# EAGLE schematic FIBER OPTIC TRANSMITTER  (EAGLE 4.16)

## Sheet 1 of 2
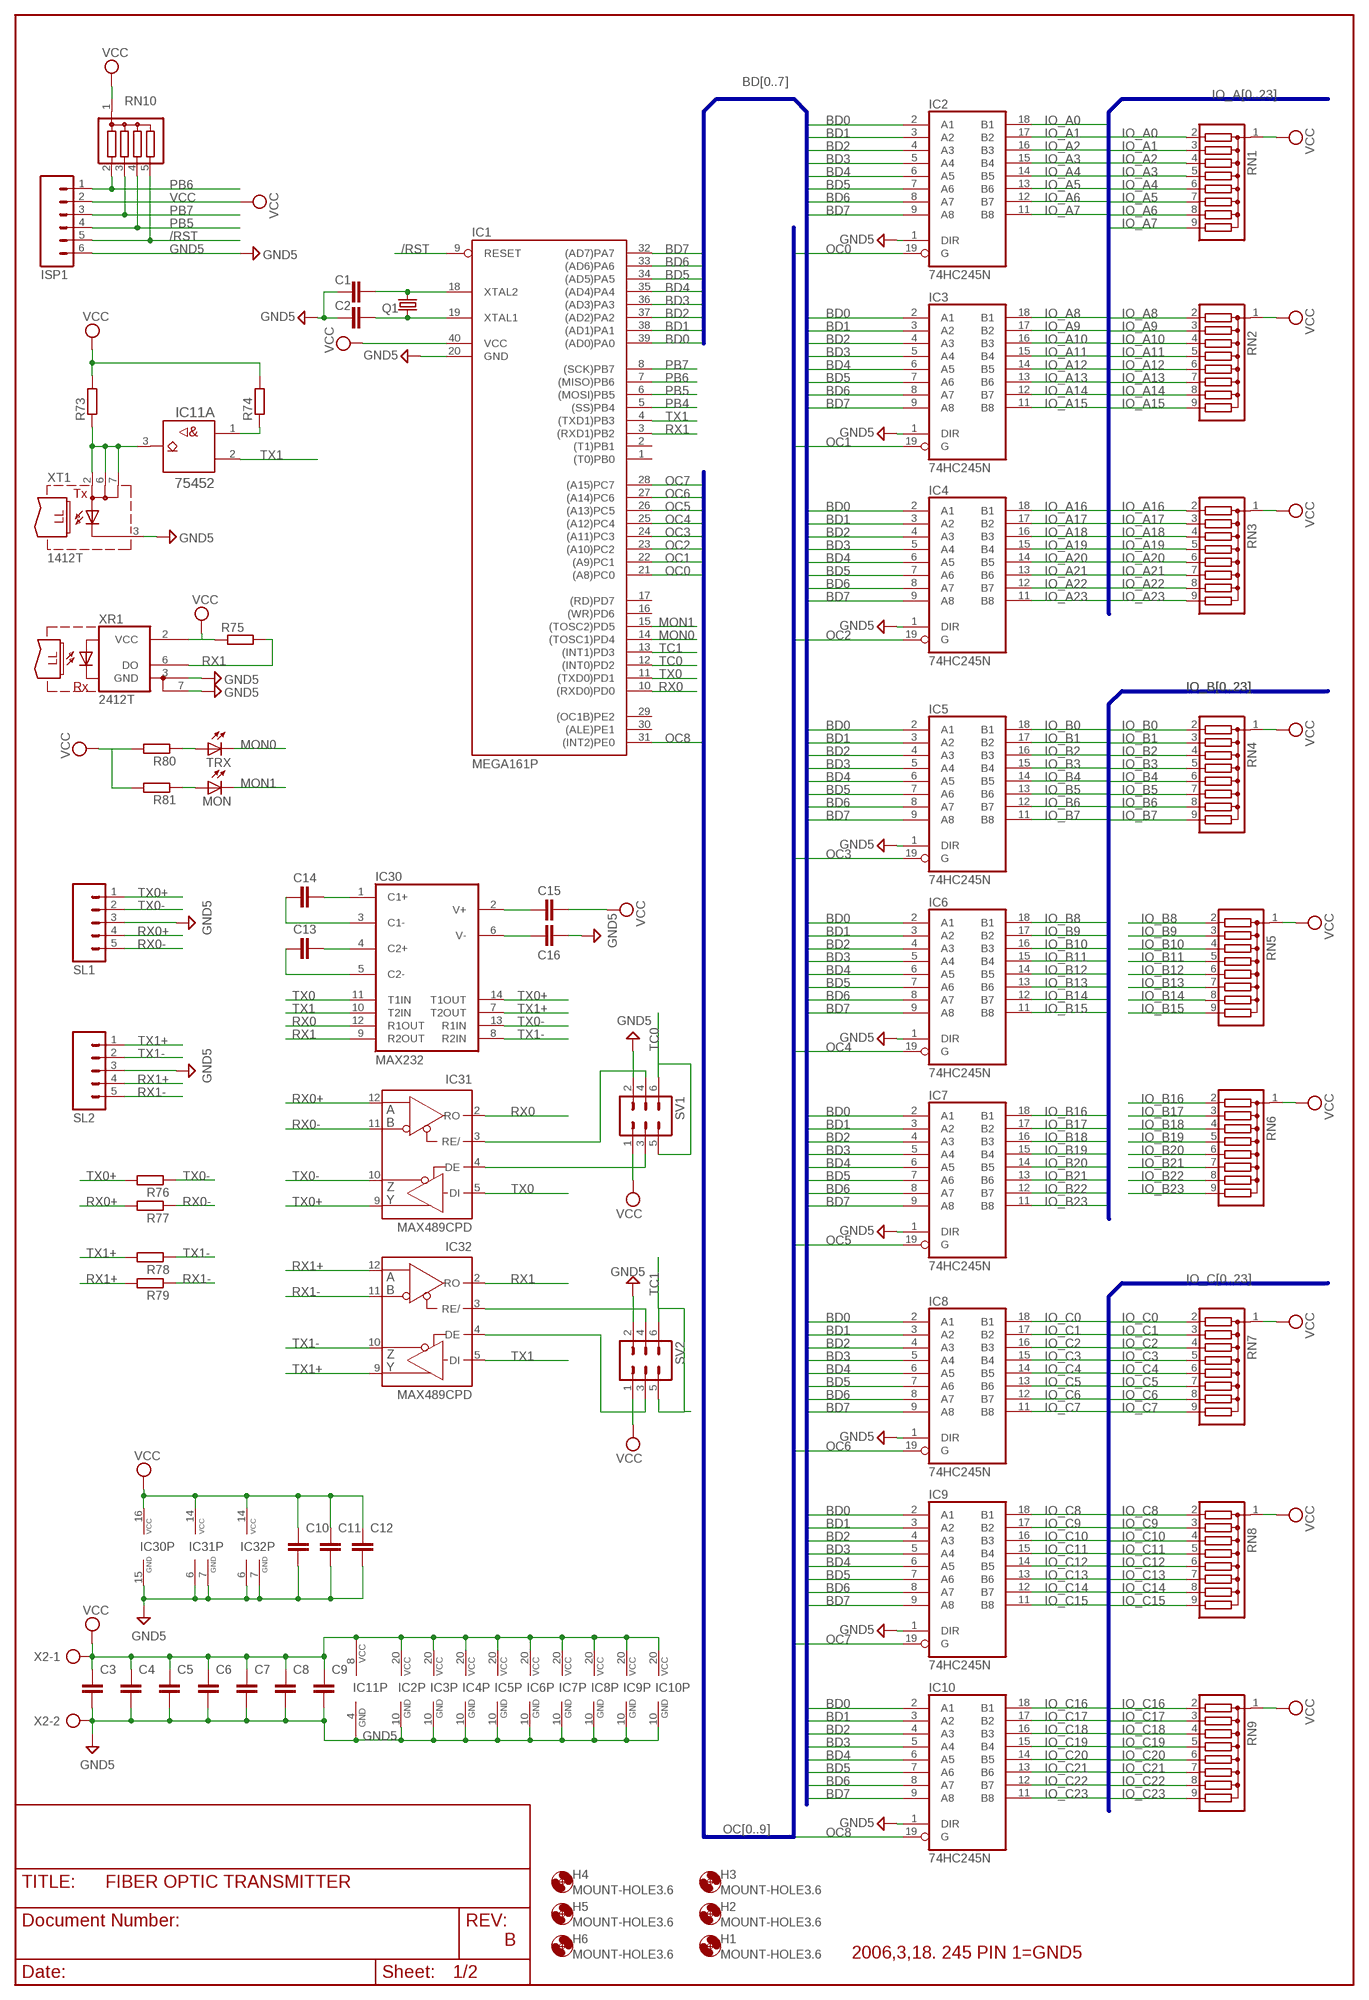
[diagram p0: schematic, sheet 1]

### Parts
C1  C5/2.5  [C5B2.5]
C2  C5/2.5  [C5B2.5]
C3  C5/2.5  [C5B2.5]
C4  C5/2.5  [C5B2.5]
C5  C5/2.5  [C5B2.5]
C6  C5/2.5  [C5B2.5]
C7  C5/2.5  [C5B2.5]
C8  C5/2.5  [C5B2.5]
C9  C5/2.5  [C5B2.5]
C10  C5/2.5  [C5B2.5]
C11  C5/2.5  [C5B2.5]
C12  C5/2.5  [C5B2.5]
C13  C5/2.5  [C5B2.5]
C14  C5/2.5  [C5B2.5]
C15  C5/2.5  [C5B2.5]
C16  C5/2.5  [C5B2.5]
H1  MOUNT-HOLE3.6  [3,6]
H2  MOUNT-HOLE3.6  [3,6]
H3  MOUNT-HOLE3.6  [3,6]
H4  MOUNT-HOLE3.6  [3,6]
H5  MOUNT-HOLE3.6  [3,6]
H6  MOUNT-HOLE3.6  [3,6]
IC1  MEGA161P  [DIL40]
IC2  74HC245N  [DIL20]
IC3  74HC245N  [DIL20]
IC4  74HC245N  [DIL20]
IC5  74HC245N  [DIL20]
IC6  74HC245N  [DIL20]
IC7  74HC245N  [DIL20]
IC8  74HC245N  [DIL20]
IC9  74HC245N  [DIL20]
IC10  74HC245N  [DIL20]
IC11  75452  75451  [DIL08]
IC30  MAX232  [DIL16]
IC31  MAX489CPD  [DIL14]
IC32  MAX489CPD  [DIL14]
ISP1  MA06  [06PA]
MON  LEDB156  [Q62902-B156]
Q1  CRYTALHC18U-V  [HC18U-V]
R73  R-EU_0207/10  [0207/10]
R74  R-EU_0207/10  [0207/10]
R75  R-EU_0207/10  [0207/10]
R76  R-EU_0207/10  [0207/10]
R77  R-EU_0207/10  [0207/10]
R78  R-EU_0207/10  [0207/10]
R79  R-EU_0207/10  [0207/10]
R80  R-EU_0207/10  [0207/10]
R81  R-EU_0207/10  [0207/10]
RN1  G08R  [SIL9]
RN2  G08R  [SIL9]
RN3  G08R  [SIL9]
RN4  G08R  [SIL9]
RN5  G08R  [SIL9]
RN6  G08R  [SIL9]
RN7  G08R  [SIL9]
RN8  G08R  [SIL9]
RN9  G08R  [SIL9]
RN10  G04R  [SIL5]
SL1  M05  [05P]
SL2  M05  [05P]
SV1  MA03-2  [MA03-2]
SV2  MA03-2  [MA03-2]
TRX  LEDB156  [Q62902-B156]
X2  AK500/2  [AK500/2]
XR1  2412T  HFBR-2412T  [HFBR-X41XT]
XT1  1412T  HFBR-1412T  [HFBR-X41XT]

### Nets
/RST: IC1.9(RESET) ISP1.5 RN10.5
BD0: IC1.39((AD0)PA0) IC2.2(A1) IC3.2(A1) IC4.2(A1) IC5.2(A1) IC6.2(A1) IC7.2(A1) IC8.2(A1) IC9.2(A1) IC10.2(A1)
BD1: IC1.38((AD1)PA1) IC2.3(A2) IC3.3(A2) IC4.3(A2) IC5.3(A2) IC6.3(A2) IC7.3(A2) IC8.3(A2) IC9.3(A2) IC10.3(A2)
BD2: IC1.37((AD2)PA2) IC2.4(A3) IC3.4(A3) IC4.4(A3) IC5.4(A3) IC6.4(A3) IC7.4(A3) IC8.4(A3) IC9.4(A3) IC10.4(A3)
BD3: IC1.36((AD3)PA3) IC2.5(A4) IC3.5(A4) IC4.5(A4) IC5.5(A4) IC6.5(A4) IC7.5(A4) IC8.5(A4) IC9.5(A4) IC10.5(A4)
BD4: IC1.35((AD4)PA4) IC2.6(A5) IC3.6(A5) IC4.6(A5) IC5.6(A5) IC6.6(A5) IC7.6(A5) IC8.6(A5) IC9.6(A5) IC10.6(A5)
BD5: IC1.34((AD5)PA5) IC2.7(A6) IC3.7(A6) IC4.7(A6) IC5.7(A6) IC6.7(A6) IC7.7(A6) IC8.7(A6) IC9.7(A6) IC10.7(A6)
BD6: IC1.33((AD6)PA6) IC2.8(A7) IC3.8(A7) IC4.8(A7) IC5.8(A7) IC6.8(A7) IC7.8(A7) IC8.8(A7) IC9.8(A7) IC10.8(A7)
BD7: IC1.32((AD7)PA7) IC2.9(A8) IC3.9(A8) IC4.9(A8) IC5.9(A8) IC6.9(A8) IC7.9(A8) IC8.9(A8) IC9.9(A8) IC10.9(A8)
GND5: C1.1 C2.1 C3.2 C4.2 C5.2 C6.2 C7.2 C8.2 C9.2 C10.2 C11.2 C12.2 C16.1 IC1.20(GND) IC2.1(DIR) IC2.10(GND) IC3.1(DIR) IC3.10(GND) IC4.1(DIR) IC4.10(GND) IC5.1(DIR) IC5.10(GND) IC6.1(DIR) IC6.10(GND) IC7.1(DIR) IC7.10(GND) IC8.1(DIR) IC8.10(GND) IC9.1(DIR) IC9.10(GND) IC10.1(DIR) IC10.10(GND) IC11.4(P:GND) IC30.15(GND) IC31.6(GND) IC31.7(GND) IC32.6(GND) IC32.7(GND) ISP1.6 SL1.3 SL2.3 SV1.2 SV2.2 X2.2 XR1.3(GND) XR1.7(GND1) XT1.3(C) ; also sheet 2
IO_A0: IC2.18(B1) RN1.2 ; also sheet 2
IO_A1: IC2.17(B2) RN1.3 ; also sheet 2
IO_A2: IC2.16(B3) RN1.4 ; also sheet 2
IO_A3: IC2.15(B4) RN1.5 ; also sheet 2
IO_A4: IC2.14(B5) RN1.6 ; also sheet 2
IO_A5: IC2.13(B6) RN1.7 ; also sheet 2
IO_A6: IC2.12(B7) RN1.8 ; also sheet 2
IO_A7: IC2.11(B8) RN1.9 ; also sheet 2
IO_A8: IC3.18(B1) RN2.2 ; also sheet 2
IO_A9: IC3.17(B2) RN2.3 ; also sheet 2
IO_A10: IC3.16(B3) RN2.4 ; also sheet 2
IO_A11: IC3.15(B4) RN2.5 ; also sheet 2
IO_A12: IC3.14(B5) RN2.6 ; also sheet 2
IO_A13: IC3.13(B6) RN2.7 ; also sheet 2
IO_A14: IC3.12(B7) RN2.8 ; also sheet 2
IO_A15: IC3.11(B8) RN2.9 ; also sheet 2
IO_A16: IC4.18(B1) RN3.2 ; also sheet 2
IO_A17: IC4.17(B2) RN3.3 ; also sheet 2
IO_A18: IC4.16(B3) RN3.4 ; also sheet 2
IO_A19: IC4.15(B4) RN3.5 ; also sheet 2
IO_A20: IC4.14(B5) RN3.6 ; also sheet 2
IO_A21: IC4.13(B6) RN3.7 ; also sheet 2
IO_A22: IC4.12(B7) RN3.8 ; also sheet 2
IO_A23: IC4.11(B8) RN3.9 ; also sheet 2
IO_B0: IC5.18(B1) RN4.2 ; also sheet 2
IO_B1: IC5.17(B2) RN4.3 ; also sheet 2
IO_B2: IC5.16(B3) RN4.4 ; also sheet 2
IO_B3: IC5.15(B4) RN4.5 ; also sheet 2
IO_B4: IC5.14(B5) RN4.6 ; also sheet 2
IO_B5: IC5.13(B6) RN4.7 ; also sheet 2
IO_B6: IC5.12(B7) RN4.8 ; also sheet 2
IO_B7: IC5.11(B8) RN4.9 ; also sheet 2
IO_B8: IC6.18(B1) RN5.2 ; also sheet 2
IO_B9: IC6.17(B2) RN5.3 ; also sheet 2
IO_B10: IC6.16(B3) RN5.4 ; also sheet 2
IO_B11: IC6.15(B4) RN5.5 ; also sheet 2
IO_B12: IC6.14(B5) RN5.6 ; also sheet 2
IO_B13: IC6.13(B6) RN5.7 ; also sheet 2
IO_B14: IC6.12(B7) RN5.8 ; also sheet 2
IO_B15: IC6.11(B8) RN5.9 ; also sheet 2
IO_B16: IC7.18(B1) RN6.2 ; also sheet 2
IO_B17: IC7.17(B2) RN6.3 ; also sheet 2
IO_B18: IC7.16(B3) RN6.4 ; also sheet 2
IO_B19: IC7.15(B4) RN6.5 ; also sheet 2
IO_B20: IC7.14(B5) RN6.6 ; also sheet 2
IO_B21: IC7.13(B6) RN6.7 ; also sheet 2
IO_B22: IC7.12(B7) RN6.8 ; also sheet 2
IO_B23: IC7.11(B8) RN6.9 ; also sheet 2
IO_C0: IC8.18(B1) RN7.2 ; also sheet 2
IO_C1: IC8.17(B2) RN7.3 ; also sheet 2
IO_C2: IC8.16(B3) RN7.4 ; also sheet 2
IO_C3: IC8.15(B4) RN7.5 ; also sheet 2
IO_C4: IC8.14(B5) RN7.6 ; also sheet 2
IO_C5: IC8.13(B6) RN7.7 ; also sheet 2
IO_C6: IC8.12(B7) RN7.8 ; also sheet 2
IO_C7: IC8.11(B8) RN7.9 ; also sheet 2
IO_C8: IC9.18(B1) RN8.2 ; also sheet 2
IO_C9: IC9.17(B2) RN8.3 ; also sheet 2
IO_C10: IC9.16(B3) RN8.4 ; also sheet 2
IO_C11: IC9.15(B4) RN8.5 ; also sheet 2
IO_C12: IC9.14(B5) RN8.6 ; also sheet 2
IO_C13: IC9.13(B6) RN8.7 ; also sheet 2
IO_C14: IC9.12(B7) RN8.8 ; also sheet 2
IO_C15: IC9.11(B8) RN8.9 ; also sheet 2
IO_C16: IC10.18(B1) RN9.2 ; also sheet 2
IO_C17: IC10.17(B2) RN9.3 ; also sheet 2
IO_C18: IC10.16(B3) RN9.4 ; also sheet 2
IO_C19: IC10.15(B4) RN9.5 ; also sheet 2
IO_C20: IC10.14(B5) RN9.6 ; also sheet 2
IO_C21: IC10.13(B6) RN9.7 ; also sheet 2
IO_C22: IC10.12(B7) RN9.8 ; also sheet 2
IO_C23: IC10.11(B8) RN9.9 ; also sheet 2
MON0: IC1.14((TOSC1)PD4) TRX.K(C)
MON1: IC1.15((TOSC2)PD5) MON.K(C)
N$73: IC11.3(A:Y) R73.1 XT1.2(A) XT1.6(A1) XT1.7(A2)
N$74: C1.2 IC1.18(XTAL2) Q1.2
N$75: IC11.1(A:A) R74.1
N$76: C2.2 IC1.19(XTAL1) Q1.1
N$77: C16.2 IC30.6(V-)
N$78: R80.1 TRX.A
N$79: MON.A R81.1
N$80: IC31.3(RE/) SV1.4
N$81: IC31.4(DE) SV1.3
N$82: IC32.3(RE/) SV2.4
N$83: IC32.4(DE) SV2.3
N$103: C14.1 IC30.1(C1+)
N$104: C14.2 IC30.3(C1-)
N$105: C13.1 IC30.4(C2+)
N$106: C13.2 IC30.5(C2-)
N$107: C15.1 IC30.2(V+)
OC0: IC1.21((A8)PC0) IC2.19(G)
OC1: IC1.22((A9)PC1) IC3.19(G)
OC2: IC1.23((A10)PC2) IC4.19(G)
OC3: IC1.24((A11)PC3) IC5.19(G)
OC4: IC1.25((A12)PC4) IC6.19(G)
OC5: IC1.26((A13)PC5) IC7.19(G)
OC6: IC1.27((A14)PC6) IC8.19(G)
OC7: IC1.28((A15)PC7) IC9.19(G)
OC8: IC1.31((INT2)PE0) IC10.19(G)
PB4: IC1.5((SS)PB4)
PB5: IC1.6((MOSI)PB5) ISP1.4 RN10.4
PB6: IC1.7((MISO)PB6) ISP1.1 RN10.2
PB7: IC1.8((SCK)PB7) ISP1.3 RN10.3
RX0: IC1.10((RXD0)PD0) IC30.12(R1OUT) IC31.2(RO)
RX0+: IC31.12(A) R77.2 SL1.4
RX0-: IC31.11(B) R77.1 SL1.5
RX1: IC1.3((RXD1)PB2) IC30.9(R2OUT) IC32.2(RO) R75.2 XR1.6(DO)
RX1+: IC32.12(A) R79.2 SL2.4
RX1-: IC32.11(B) R79.1 SL2.5
TC0: IC1.12((INT0)PD2) SV1.5 SV1.6
TC1: IC1.13((INT1)PD3) SV2.5 SV2.6
TX0: IC1.11((TXD0)PD1) IC30.11(T1IN) IC31.5(DI)
TX0+: IC30.14(T1OUT) IC31.9(Y) R76.2 SL1.1
TX0-: IC30.13(R1IN) IC31.10(Z) R76.1 SL1.2
TX1: IC1.4((TXD1)PB3) IC11.2(A:B) IC30.10(T2IN) IC32.5(DI)
TX1+: IC30.7(T2OUT) IC32.9(Y) R78.2 SL2.1
TX1-: IC30.8(R2IN) IC32.10(Z) R78.1 SL2.2
VCC: C3.1 C4.1 C5.1 C6.1 C7.1 C8.1 C9.1 C10.1 C11.1 C12.1 C15.2 IC1.40(VCC) IC2.20(VCC) IC3.20(VCC) IC4.20(VCC) IC5.20(VCC) IC6.20(VCC) IC7.20(VCC) IC8.20(VCC) IC9.20(VCC) IC10.20(VCC) IC11.8(P:VCC) IC30.16(VCC) IC31.14(VCC) IC32.14(VCC) ISP1.2 R73.2 R74.2 R75.1 R80.2 R81.2 RN1.1 RN2.1 RN3.1 RN4.1 RN5.1 RN6.1 RN7.1 RN8.1 RN9.1 RN10.1 SV1.1 SV2.1 X2.1 XR1.2(VCC)
Unconnected: IC1.1((T0)PB0) IC1.2((T1)PB1) IC1.16((WR)PD6) IC1.17((RD)PD7) IC1.29((OC1B)PE2) IC1.30((ALE)PE1) IC11.5(B:Y) IC11.6(B:A) IC11.7(B:B) IC31.1(NC) IC31.8(NC) IC31.13(NC) IC32.1(NC) IC32.8(NC) IC32.13(NC)

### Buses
BD[0..7]
OC[0..9]
IO_A[0..23]
IO_C[0..23]
IO_B[0..23]

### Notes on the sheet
- B
- 2006,3,18. 245 PIN 1=GND5

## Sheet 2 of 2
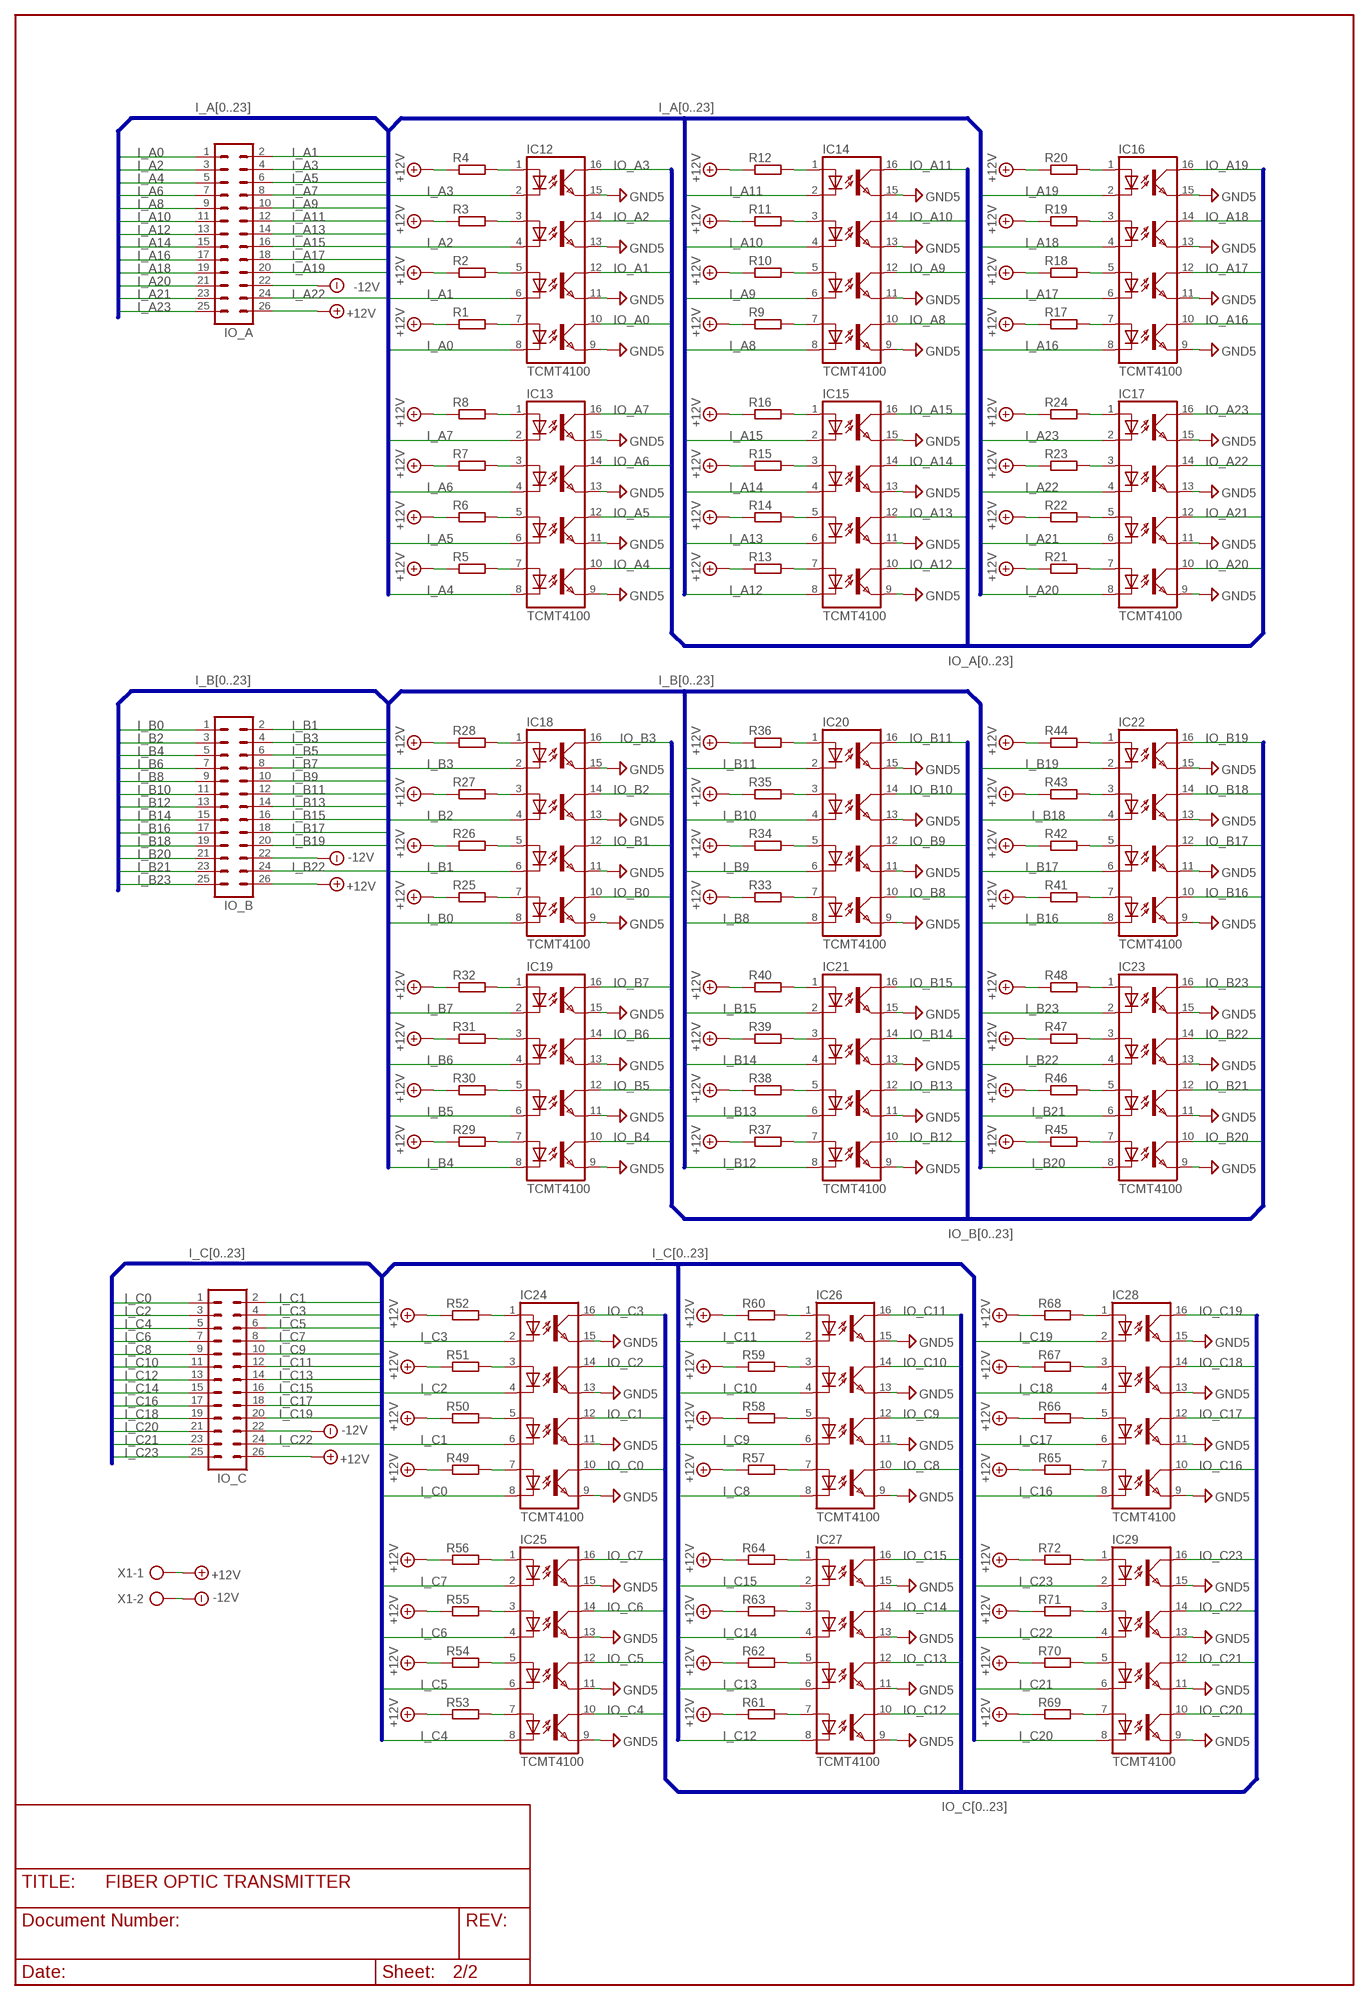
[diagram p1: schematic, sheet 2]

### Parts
IC12  TCMT4100  [SOIC16]
IC13  TCMT4100  [SOIC16]
IC14  TCMT4100  [SOIC16]
IC15  TCMT4100  [SOIC16]
IC16  TCMT4100  [SOIC16]
IC17  TCMT4100  [SOIC16]
IC18  TCMT4100  [SOIC16]
IC19  TCMT4100  [SOIC16]
IC20  TCMT4100  [SOIC16]
IC21  TCMT4100  [SOIC16]
IC22  TCMT4100  [SOIC16]
IC23  TCMT4100  [SOIC16]
IC24  TCMT4100  [SOIC16]
IC25  TCMT4100  [SOIC16]
IC26  TCMT4100  [SOIC16]
IC27  TCMT4100  [SOIC16]
IC28  TCMT4100  [SOIC16]
IC29  TCMT4100  [SOIC16]
IO_A  26V  [26V]
IO_B  26V  [26V]
IO_C  26V  [26V]
R1  R-EU_0207/10  [0207/10]
R2  R-EU_0207/10  [0207/10]
R3  R-EU_0207/10  [0207/10]
R4  R-EU_0207/10  [0207/10]
R5  R-EU_0207/10  [0207/10]
R6  R-EU_0207/10  [0207/10]
R7  R-EU_0207/10  [0207/10]
R8  R-EU_0207/10  [0207/10]
R9  R-EU_0207/10  [0207/10]
R10  R-EU_0207/10  [0207/10]
R11  R-EU_0207/10  [0207/10]
R12  R-EU_0207/10  [0207/10]
R13  R-EU_0207/10  [0207/10]
R14  R-EU_0207/10  [0207/10]
R15  R-EU_0207/10  [0207/10]
R16  R-EU_0207/10  [0207/10]
R17  R-EU_0207/10  [0207/10]
R18  R-EU_0207/10  [0207/10]
R19  R-EU_0207/10  [0207/10]
R20  R-EU_0207/10  [0207/10]
R21  R-EU_0207/10  [0207/10]
R22  R-EU_0207/10  [0207/10]
R23  R-EU_0207/10  [0207/10]
R24  R-EU_0207/10  [0207/10]
R25  R-EU_0207/10  [0207/10]
R26  R-EU_0207/10  [0207/10]
R27  R-EU_0207/10  [0207/10]
R28  R-EU_0207/10  [0207/10]
R29  R-EU_0207/10  [0207/10]
R30  R-EU_0207/10  [0207/10]
R31  R-EU_0207/10  [0207/10]
R32  R-EU_0207/10  [0207/10]
R33  R-EU_0207/10  [0207/10]
R34  R-EU_0207/10  [0207/10]
R35  R-EU_0207/10  [0207/10]
R36  R-EU_0207/10  [0207/10]
R37  R-EU_0207/10  [0207/10]
R38  R-EU_0207/10  [0207/10]
R39  R-EU_0207/10  [0207/10]
R40  R-EU_0207/10  [0207/10]
R41  R-EU_0207/10  [0207/10]
R42  R-EU_0207/10  [0207/10]
R43  R-EU_0207/10  [0207/10]
R44  R-EU_0207/10  [0207/10]
R45  R-EU_0207/10  [0207/10]
R46  R-EU_0207/10  [0207/10]
R47  R-EU_0207/10  [0207/10]
R48  R-EU_0207/10  [0207/10]
R49  R-EU_0207/10  [0207/10]
R50  R-EU_0207/10  [0207/10]
R51  R-EU_0207/10  [0207/10]
R52  R-EU_0207/10  [0207/10]
R53  R-EU_0207/10  [0207/10]
R54  R-EU_0207/10  [0207/10]
R55  R-EU_0207/10  [0207/10]
R56  R-EU_0207/10  [0207/10]
R57  R-EU_0207/10  [0207/10]
R58  R-EU_0207/10  [0207/10]
R59  R-EU_0207/10  [0207/10]
R60  R-EU_0207/10  [0207/10]
R61  R-EU_0207/10  [0207/10]
R62  R-EU_0207/10  [0207/10]
R63  R-EU_0207/10  [0207/10]
R64  R-EU_0207/10  [0207/10]
R65  R-EU_0207/10  [0207/10]
R66  R-EU_0207/10  [0207/10]
R67  R-EU_0207/10  [0207/10]
R68  R-EU_0207/10  [0207/10]
R69  R-EU_0207/10  [0207/10]
R70  R-EU_0207/10  [0207/10]
R71  R-EU_0207/10  [0207/10]
R72  R-EU_0207/10  [0207/10]
X1  AK500/2  [AK500/2]

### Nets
+12V: IO_A.26 IO_B.26 IO_C.26 R1.1 R2.1 R3.1 R4.1 R5.1 R6.1 R7.1 R8.1 R9.1 R10.1 R11.1 R12.1 R13.1 R14.1 R15.1 R16.1 R17.1 R18.1 R19.1 R20.1 R21.1 R22.1 R23.1 R24.1 R25.1 R26.1 R27.1 R28.1 R29.1 R30.1 R31.1 R32.1 R33.1 R34.1 R35.1 R36.1 R37.1 R38.1 R39.1 R40.1 R41.1 R42.1 R43.1 R44.1 R45.1 R46.1 R47.1 R48.1 R49.1 R50.1 R51.1 R52.1 R53.1 R54.1 R55.1 R56.1 R57.1 R58.1 R59.1 R60.1 R61.1 R62.1 R63.1 R64.1 R65.1 R66.1 R67.1 R68.1 R69.1 R70.1 R71.1 R72.1 X1.1
-12V: IO_A.22 IO_B.22 IO_C.22 X1.2
GND5: IC12.9(EMIT3) IC12.11(EMIT2) IC12.13(EMIT1) IC12.15(EMIT) IC13.9(EMIT3) IC13.11(EMIT2) IC13.13(EMIT1) IC13.15(EMIT) IC14.9(EMIT3) IC14.11(EMIT2) IC14.13(EMIT1) IC14.15(EMIT) IC15.9(EMIT3) IC15.11(EMIT2) IC15.13(EMIT1) IC15.15(EMIT) IC16.9(EMIT3) IC16.11(EMIT2) IC16.13(EMIT1) IC16.15(EMIT) IC17.9(EMIT3) IC17.11(EMIT2) IC17.13(EMIT1) IC17.15(EMIT) IC18.9(EMIT3) IC18.11(EMIT2) IC18.13(EMIT1) IC18.15(EMIT) IC19.9(EMIT3) IC19.11(EMIT2) IC19.13(EMIT1) IC19.15(EMIT) IC20.9(EMIT3) IC20.11(EMIT2) IC20.13(EMIT1) IC20.15(EMIT) IC21.9(EMIT3) IC21.11(EMIT2) IC21.13(EMIT1) IC21.15(EMIT) IC22.9(EMIT3) IC22.11(EMIT2) IC22.13(EMIT1) IC22.15(EMIT) IC23.9(EMIT3) IC23.11(EMIT2) IC23.13(EMIT1) IC23.15(EMIT) IC24.9(EMIT3) IC24.11(EMIT2) IC24.13(EMIT1) IC24.15(EMIT) IC25.9(EMIT3) IC25.11(EMIT2) IC25.13(EMIT1) IC25.15(EMIT) IC26.9(EMIT3) IC26.11(EMIT2) IC26.13(EMIT1) IC26.15(EMIT) IC27.9(EMIT3) IC27.11(EMIT2) IC27.13(EMIT1) IC27.15(EMIT) IC28.9(EMIT3) IC28.11(EMIT2) IC28.13(EMIT1) IC28.15(EMIT) IC29.9(EMIT3) IC29.11(EMIT2) IC29.13(EMIT1) IC29.15(EMIT) ; also sheet 1
I_A0: IC12.8(C3) IO_A.1
I_A1: IC12.6(C2) IO_A.2
I_A2: IC12.4(C1) IO_A.3
I_A3: IC12.2(C) IO_A.4
I_A4: IC13.8(C3) IO_A.5
I_A5: IC13.6(C2) IO_A.6
I_A6: IC13.4(C1) IO_A.7
I_A7: IC13.2(C) IO_A.8
I_A8: IC14.8(C3) IO_A.9
I_A9: IC14.6(C2) IO_A.10
I_A10: IC14.4(C1) IO_A.11
I_A11: IC14.2(C) IO_A.12
I_A12: IC15.8(C3) IO_A.13
I_A13: IC15.6(C2) IO_A.14
I_A14: IC15.4(C1) IO_A.15
I_A15: IC15.2(C) IO_A.16
I_A16: IC16.8(C3) IO_A.17
I_A17: IC16.6(C2) IO_A.18
I_A18: IC16.4(C1) IO_A.19
I_A19: IC16.2(C) IO_A.20
I_A20: IC17.8(C3) IO_A.21
I_A21: IC17.6(C2) IO_A.23
I_A22: IC17.4(C1) IO_A.24
I_A23: IC17.2(C) IO_A.25
I_B0: IC18.8(C3) IO_B.1
I_B1: IC18.6(C2) IO_B.2
I_B2: IC18.4(C1) IO_B.3
I_B3: IC18.2(C) IO_B.4
I_B4: IC19.8(C3) IO_B.5
I_B5: IC19.6(C2) IO_B.6
I_B6: IC19.4(C1) IO_B.7
I_B7: IC19.2(C) IO_B.8
I_B8: IC20.8(C3) IO_B.9
I_B9: IC20.6(C2) IO_B.10
I_B10: IC20.4(C1) IO_B.11
I_B11: IC20.2(C) IO_B.12
I_B12: IC21.8(C3) IO_B.13
I_B13: IC21.6(C2) IO_B.14
I_B14: IC21.4(C1) IO_B.15
I_B15: IC21.2(C) IO_B.16
I_B16: IC22.8(C3) IO_B.17
I_B17: IC22.6(C2) IO_B.18
I_B18: IC22.4(C1) IO_B.19
I_B19: IC22.2(C) IO_B.20
I_B20: IC23.8(C3) IO_B.21
I_B21: IC23.6(C2) IO_B.23
I_B22: IC23.4(C1) IO_B.24
I_B23: IC23.2(C) IO_B.25
I_C0: IC24.8(C3) IO_C.1
I_C1: IC24.6(C2) IO_C.2
I_C2: IC24.4(C1) IO_C.3
I_C3: IC24.2(C) IO_C.4
I_C4: IC25.8(C3) IO_C.5
I_C5: IC25.6(C2) IO_C.6
I_C6: IC25.4(C1) IO_C.7
I_C7: IC25.2(C) IO_C.8
I_C8: IC26.8(C3) IO_C.9
I_C9: IC26.6(C2) IO_C.10
I_C10: IC26.4(C1) IO_C.11
I_C11: IC26.2(C) IO_C.12
I_C12: IC27.8(C3) IO_C.13
I_C13: IC27.6(C2) IO_C.14
I_C14: IC27.4(C1) IO_C.15
I_C15: IC27.2(C) IO_C.16
I_C16: IC28.8(C3) IO_C.17
I_C17: IC28.6(C2) IO_C.18
I_C18: IC28.4(C1) IO_C.19
I_C19: IC28.2(C) IO_C.20
I_C20: IC29.8(C3) IO_C.21
I_C21: IC29.6(C2) IO_C.23
I_C22: IC29.4(C1) IO_C.24
I_C23: IC29.2(C) IO_C.25
IO_A0: IC12.10(COL3) ; also sheet 1
IO_A1: IC12.12(COL2) ; also sheet 1
IO_A2: IC12.14(COL1) ; also sheet 1
IO_A3: IC12.16(COL) ; also sheet 1
IO_A4: IC13.10(COL3) ; also sheet 1
IO_A5: IC13.12(COL2) ; also sheet 1
IO_A6: IC13.14(COL1) ; also sheet 1
IO_A7: IC13.16(COL) ; also sheet 1
IO_A8: IC14.10(COL3) ; also sheet 1
IO_A9: IC14.12(COL2) ; also sheet 1
IO_A10: IC14.14(COL1) ; also sheet 1
IO_A11: IC14.16(COL) ; also sheet 1
IO_A12: IC15.10(COL3) ; also sheet 1
IO_A13: IC15.12(COL2) ; also sheet 1
IO_A14: IC15.14(COL1) ; also sheet 1
IO_A15: IC15.16(COL) ; also sheet 1
IO_A16: IC16.10(COL3) ; also sheet 1
IO_A17: IC16.12(COL2) ; also sheet 1
IO_A18: IC16.14(COL1) ; also sheet 1
IO_A19: IC16.16(COL) ; also sheet 1
IO_A20: IC17.10(COL3) ; also sheet 1
IO_A21: IC17.12(COL2) ; also sheet 1
IO_A22: IC17.14(COL1) ; also sheet 1
IO_A23: IC17.16(COL) ; also sheet 1
IO_B0: IC18.10(COL3) ; also sheet 1
IO_B1: IC18.12(COL2) ; also sheet 1
IO_B2: IC18.14(COL1) ; also sheet 1
IO_B3: IC18.16(COL) ; also sheet 1
IO_B4: IC19.10(COL3) ; also sheet 1
IO_B5: IC19.12(COL2) ; also sheet 1
IO_B6: IC19.14(COL1) ; also sheet 1
IO_B7: IC19.16(COL) ; also sheet 1
IO_B8: IC20.10(COL3) ; also sheet 1
IO_B9: IC20.12(COL2) ; also sheet 1
IO_B10: IC20.14(COL1) ; also sheet 1
IO_B11: IC20.16(COL) ; also sheet 1
IO_B12: IC21.10(COL3) ; also sheet 1
IO_B13: IC21.12(COL2) ; also sheet 1
IO_B14: IC21.14(COL1) ; also sheet 1
IO_B15: IC21.16(COL) ; also sheet 1
IO_B16: IC22.10(COL3) ; also sheet 1
IO_B17: IC22.12(COL2) ; also sheet 1
IO_B18: IC22.14(COL1) ; also sheet 1
IO_B19: IC22.16(COL) ; also sheet 1
IO_B20: IC23.10(COL3) ; also sheet 1
IO_B21: IC23.12(COL2) ; also sheet 1
IO_B22: IC23.14(COL1) ; also sheet 1
IO_B23: IC23.16(COL) ; also sheet 1
IO_C0: IC24.10(COL3) ; also sheet 1
IO_C1: IC24.12(COL2) ; also sheet 1
IO_C2: IC24.14(COL1) ; also sheet 1
IO_C3: IC24.16(COL) ; also sheet 1
IO_C4: IC25.10(COL3) ; also sheet 1
IO_C5: IC25.12(COL2) ; also sheet 1
IO_C6: IC25.14(COL1) ; also sheet 1
IO_C7: IC25.16(COL) ; also sheet 1
IO_C8: IC26.10(COL3) ; also sheet 1
IO_C9: IC26.12(COL2) ; also sheet 1
IO_C10: IC26.14(COL1) ; also sheet 1
IO_C11: IC26.16(COL) ; also sheet 1
IO_C12: IC27.10(COL3) ; also sheet 1
IO_C13: IC27.12(COL2) ; also sheet 1
IO_C14: IC27.14(COL1) ; also sheet 1
IO_C15: IC27.16(COL) ; also sheet 1
IO_C16: IC28.10(COL3) ; also sheet 1
IO_C17: IC28.12(COL2) ; also sheet 1
IO_C18: IC28.14(COL1) ; also sheet 1
IO_C19: IC28.16(COL) ; also sheet 1
IO_C20: IC29.10(COL3) ; also sheet 1
IO_C21: IC29.12(COL2) ; also sheet 1
IO_C22: IC29.14(COL1) ; also sheet 1
IO_C23: IC29.16(COL) ; also sheet 1
N$1: IC12.1(A) R4.2
N$2: IC12.3(A1) R3.2
N$3: IC12.5(A2) R2.2
N$4: IC12.7(A3) R1.2
N$5: IC13.1(A) R8.2
N$6: IC13.3(A1) R7.2
N$7: IC13.5(A2) R6.2
N$8: IC13.7(A3) R5.2
N$9: IC14.1(A) R12.2
N$10: IC14.3(A1) R11.2
N$11: IC14.5(A2) R10.2
N$12: IC14.7(A3) R9.2
N$13: IC15.1(A) R16.2
N$14: IC15.3(A1) R15.2
N$15: IC15.5(A2) R14.2
N$16: IC15.7(A3) R13.2
N$17: IC16.1(A) R20.2
N$18: IC16.3(A1) R19.2
N$19: IC16.5(A2) R18.2
N$20: IC16.7(A3) R17.2
N$21: IC17.1(A) R24.2
N$22: IC17.3(A1) R23.2
N$23: IC17.5(A2) R22.2
N$24: IC17.7(A3) R21.2
N$25: IC18.1(A) R28.2
N$26: IC18.3(A1) R27.2
N$27: IC18.5(A2) R26.2
N$28: IC18.7(A3) R25.2
N$29: IC19.1(A) R32.2
N$30: IC19.3(A1) R31.2
N$31: IC19.5(A2) R30.2
N$32: IC19.7(A3) R29.2
N$33: IC20.1(A) R36.2
N$34: IC20.3(A1) R35.2
N$35: IC20.5(A2) R34.2
N$36: IC20.7(A3) R33.2
N$37: IC21.1(A) R40.2
N$38: IC21.3(A1) R39.2
N$39: IC21.5(A2) R38.2
N$40: IC21.7(A3) R37.2
N$41: IC22.1(A) R44.2
N$42: IC22.3(A1) R43.2
N$43: IC22.5(A2) R42.2
N$44: IC22.7(A3) R41.2
N$45: IC23.1(A) R48.2
N$46: IC23.3(A1) R47.2
N$47: IC23.5(A2) R46.2
N$48: IC23.7(A3) R45.2
N$49: IC24.1(A) R52.2
N$50: IC24.3(A1) R51.2
N$51: IC24.5(A2) R50.2
N$52: IC24.7(A3) R49.2
N$53: IC25.1(A) R56.2
N$54: IC25.3(A1) R55.2
N$55: IC25.5(A2) R54.2
N$56: IC25.7(A3) R53.2
N$57: IC26.1(A) R60.2
N$58: IC26.3(A1) R59.2
N$59: IC26.5(A2) R58.2
N$60: IC26.7(A3) R57.2
N$61: IC27.1(A) R64.2
N$62: IC27.3(A1) R63.2
N$63: IC27.5(A2) R62.2
N$64: IC27.7(A3) R61.2
N$65: IC28.1(A) R68.2
N$66: IC28.3(A1) R67.2
N$67: IC28.5(A2) R66.2
N$68: IC28.7(A3) R65.2
N$69: IC29.1(A) R72.2
N$70: IC29.3(A1) R71.2
N$71: IC29.5(A2) R70.2
N$72: IC29.7(A3) R69.2

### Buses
I_A[0..23]
IO_A[0..23]
I_B[0..23]
IO_B[0..23]
I_C[0..23]
IO_C[0..23]

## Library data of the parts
C1-C16 = capacitor-wima:C: CAPACITOR
H1-H6 = holes:MOUNT-HOLE: MOUNTING HOLE with drill center marker
IC1 = avr:MEGA161*P: MICROCONTROLLER 16 Kbytes FLASH, 512 bytes EEPROM 1 Kbytes SRAM dual UART hardware multiplier
IC2-IC10 = 74xx-eu:74*245: Octal BUS TRANSCEIVER, 3-state
IC11 = 75_driver:75451
IC12-IC29 = optocoupler:TCMT4100
IC30 = maxim:MAX232: RS232 TRANSEIVER
IC31 IC32 = maxim:MAX489CPD: RS485 TRANSEIVER
IO_A IO_B IO_C = con-harting-v:26V: CONNECTOR
ISP1 = con-amp-quick:MA06: AMP QUICK CONNECTOR
MON TRX = led:LED: LED
Q1 = crystal:CRYTAL: CRYSTAL
R1-R81 = rcl:R-EU_: RESISTOR, European symbol
RN1-RN9 = resistor-sil:G08R: SIL RESISTOR
RN10 = resistor-sil:G04R: SIL RESISTOR
SL1 SL2 = con-amp-quick:M05: AMP QUICK CONNECTOR
SV1 SV2 = con-lstb:MA03-2: PIN HEADER
X1 X2 = con-ptr500:AK500/2: CONNECTOR
XR1 = fiber-optic-hp:HFBR-2412T: RECEIVER low cost miniature fiber optic component, ST housed, TX standard power
XT1 = fiber-optic-hp:HFBR-1412T: TRANSMITTER low cost miniature fiber optic component, 5-MBd high performance link, vertical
